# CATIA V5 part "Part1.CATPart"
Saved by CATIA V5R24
Part number: Part1
Bounding box of the stored display mesh (mm): x 0 to 20, y -65 to 65, z -10 to 10
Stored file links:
  G:\_CAD수업\DMU_paradoxes\inversion\Part1.CATPart
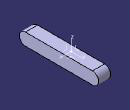
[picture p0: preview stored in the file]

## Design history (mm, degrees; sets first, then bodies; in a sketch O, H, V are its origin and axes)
AxisSystem1: origin (0, 0, 0), X (1, 0, 0), Y (0, 1, 0), Z (0, 0, 1)
Body1 (main body)
  Sketch1 on YZ plane of AxisSystem1, origin (0, 0, 0), H (0, 1, 0), V (0, 0, 1)
    construction line L1 (-55, 0) -> (55, 0)
    point P1 (-55, 0)
    line L2 (-55, 10) -> (55, 10)
    line L3 (55, -10) -> (-55, -10)
    arc A1 centre (55, 0) radius 10 from (55, 10) to (55, -10) cw
    arc A2 centre (-55, 0) radius 10 from (-55, -10) to (-55, 10) cw
    distance L1 L2 = 10
    coincidence: P1 H
    horizontal: L1 H
    tangency: A1 L2, A2 L2, A1 L3, A2 L3
  Pad1: profile Sketch1, direction (1, 0, 0), length 20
